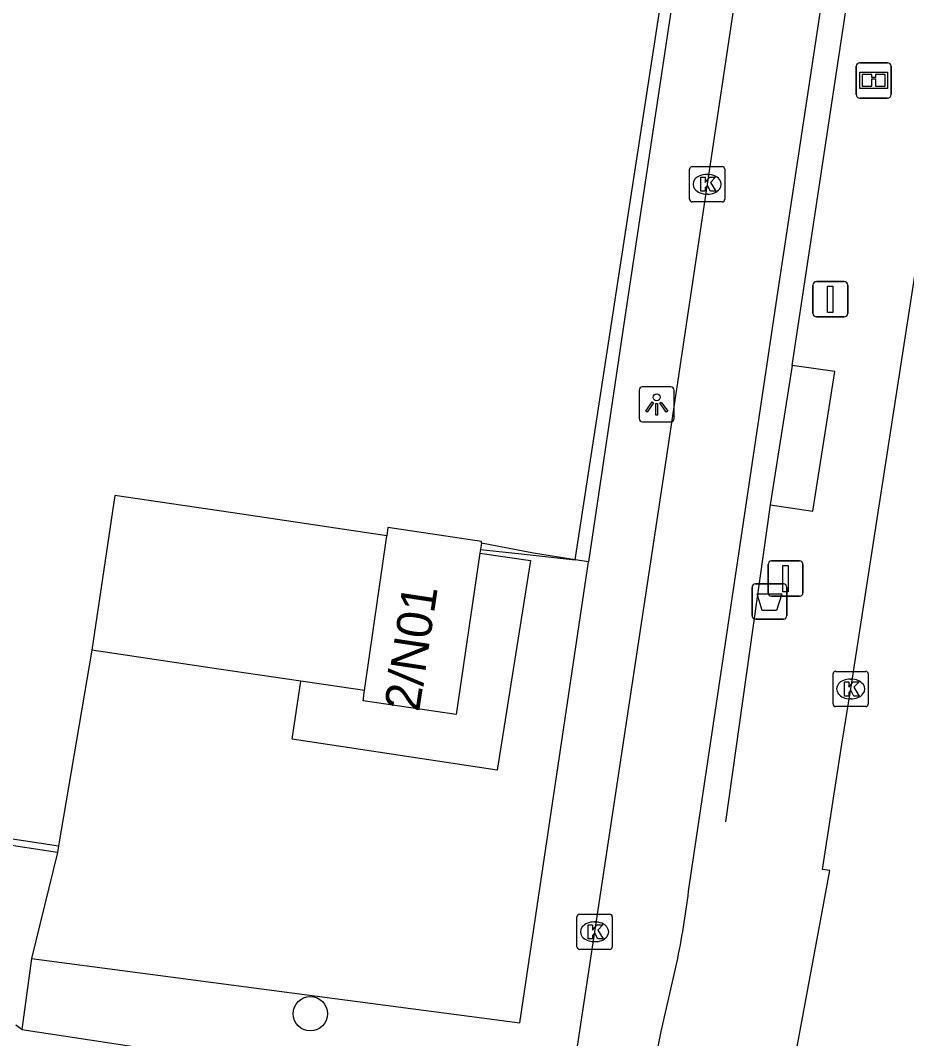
# Model space of a CAD drawing. Extents: x 161094 to 161705, y 379509 to 380907.
# Drawn here: x 161586.2 to 161611.36, y 380439.45 to 380468.34 of the extents above; entities that cross this region are included whole.
import ezdxf

# ---------------------------------------------------------------- set-up
doc = ezdxf.new("R2010")
doc.units = 0
for name, color, linetype in [('IMGEO_Afsluitpaal', 7, 'Continuous'), ('IMGEO_Afvalbak', 7, 'Continuous'), ('IMGEO_Boom', 7, 'Continuous'), ('IMGEO_Fietspad_gesloten', 7, 'Continuous'), ('IMGEO_Groenvoorziening', 7, 'Continuous'), ('IMGEO_Hek', 7, 'Continuous'), ('IMGEO_Informatiebord', 7, 'Continuous'), ('IMGEO_Kolk', 7, 'Continuous'), ('IMGEO_Lichtpunt', 7, 'Continuous'), ('IMGEO_Loofbos', 7, 'Continuous'), ('IMGEO_OVBaan_gesloten', 7, 'Continuous'), ('IMGEO_Pand', 7, 'Continuous'), ('IMGEO_Pand_nummerreeks', 7, 'Continuous'), ('IMGEO_Voetpad_open', 7, 'Continuous')]:
    doc.layers.add(name, color=color, linetype=linetype)

msp = doc.modelspace()

# ---------------------------------------------------------------- linework, layer by layer
at = {"layer": 'IMGEO_Afsluitpaal'}
for p, q in [((161608.694, 380460.028), (161608.694, 380460.828)), ((161608.694, 380460.828), (161608.694, 380460.028)), ((161608.794, 380460.928), (161609.584, 380460.928)), ((161609.584, 380460.928), (161608.794, 380460.928)), ((161609.684, 380460.828), (161609.684, 380460.028)), ((161609.684, 380460.028), (161609.684, 380460.828)), ((161609.584, 380459.928), (161608.794, 380459.928)), ((161608.794, 380459.928), (161609.584, 380459.928)), ((161607.424, 380452.103), (161607.424, 380452.903)), ((161607.424, 380452.903), (161607.424, 380452.103)), ((161607.524, 380453.003), (161608.314, 380453.003)), ((161608.314, 380453.003), (161607.524, 380453.003)), ((161608.414, 380452.903), (161608.414, 380452.103)), ((161608.414, 380452.103), (161608.414, 380452.903)), ((161608.314, 380452.003), (161607.524, 380452.003)), ((161607.524, 380452.003), (161608.314, 380452.003))]:
    msp.add_line(p, q, dxfattribs=at)
for points in [[(161609.114, 380460.803), (161609.264, 380460.803), (161609.264, 380460.053), (161609.114, 380460.053), (161609.114, 380460.803)], [(161607.844, 380452.878), (161607.994, 380452.878), (161607.994, 380452.128), (161607.844, 380452.128), (161607.844, 380452.878)]]:
    msp.add_lwpolyline(points, dxfattribs=at)
for centre, start, end in [((161608.794, 380460.828), 90, 180), ((161608.794, 380460.828), 90, 180), ((161609.584, 380460.828), 0, 90), ((161609.584, 380460.828), 360, 90), ((161608.794, 380460.028), 180, 270), ((161608.794, 380460.028), 180, 270), ((161609.584, 380460.028), 270, 0), ((161609.584, 380460.028), 270, 0), ((161607.524, 380452.903), 90, 180), ((161607.524, 380452.903), 90, 180), ((161608.314, 380452.903), 0, 90), ((161608.314, 380452.903), 360, 90), ((161607.524, 380452.103), 180, 270), ((161607.524, 380452.103), 180, 270), ((161608.314, 380452.103), 270, 0), ((161608.314, 380452.103), 270, 0)]:
    msp.add_arc(centre, 0.1, start, end, dxfattribs=at)
at = {"layer": 'IMGEO_Afvalbak'}
for p, q in [((161607.068, 380452.353), (161607.858, 380452.353)), ((161607.858, 380452.353), (161607.068, 380452.353)), ((161606.968, 380451.453), (161606.968, 380452.253)), ((161606.968, 380452.253), (161606.968, 380451.453)), ((161607.958, 380452.253), (161607.958, 380451.453)), ((161607.958, 380451.453), (161607.958, 380452.253)), ((161607.858, 380451.353), (161607.068, 380451.353)), ((161607.068, 380451.353), (161607.858, 380451.353))]:
    msp.add_line(p, q, dxfattribs=at)
msp.add_lwpolyline([(161607.111, 380452.067), (161607.815, 380452.067), (161607.666, 380451.597), (161607.26, 380451.597), (161607.111, 380452.067)], dxfattribs=at)
for centre, start, end in [((161607.068, 380452.253), 90, 180), ((161607.068, 380452.253), 90, 180), ((161607.858, 380452.253), 0, 90), ((161607.858, 380452.253), 360, 90), ((161607.068, 380451.453), 180, 270), ((161607.068, 380451.453), 180, 270), ((161607.858, 380451.453), 270, 0), ((161607.858, 380451.453), 270, 0)]:
    msp.add_arc(centre, 0.1, start, end, dxfattribs=at)
at = {"layer": 'IMGEO_Boom'}
msp.add_circle((161594.431, 380440.157), 0.489, dxfattribs=at)
at = {"layer": 'IMGEO_Fietspad_gesloten'}
for points in [[(161612.72, 380509.065), (161611.793, 380503.916), (161610.143, 380493.022), (161609.084, 380485.902), (161608.039, 380479.352), (161605.695, 380463.691), (161604.472, 380455.541), (161602.499, 380442.481), (161602, 380439.232)], [(161605.166, 380443.632), (161607.677, 380460.497), (161610.329, 380477.98), (161611.098, 380483.56)], [(161603.991, 380437.681), (161604.389, 380439.652), (161604.832, 380441.602)]]:
    msp.add_lwpolyline(points, dxfattribs=at)
msp.add_arc((161582.397, 380446.336), 22.929, 348.0854, 353.228, dxfattribs=at)
at = {"layer": 'IMGEO_Groenvoorziening'}
msp.add_lwpolyline([(161587.284, 380444.922), (161587.251, 380444.727)], dxfattribs=at)
at = {"layer": 'IMGEO_Hek'}
for points in [[(161599.258, 380453.328), (161600.417, 380453.203), (161601.946, 380453.038), (161608.829, 380497.747), (161609.712, 380502.964)], [(161608.111, 380458.552), (161611.815, 380483.076), (161613.253, 380482.731)], [(161587.251, 380444.727), (161434.436, 380467.982)], [(161607.482, 380454.596), (161606.219, 380445.605)], [(161588.227, 380450.468), (161587.284, 380444.922)], [(161587.284, 380444.922), (161587.251, 380444.727)]]:
    msp.add_lwpolyline(points, dxfattribs=at)
at = {"layer": 'IMGEO_Informatiebord'}
for p, q in [((161609.924, 380466.237), (161609.924, 380467.037)), ((161609.924, 380467.037), (161609.924, 380466.237)), ((161610.024, 380467.137), (161610.814, 380467.137)), ((161610.814, 380467.137), (161610.024, 380467.137)), ((161610.914, 380467.037), (161610.914, 380466.237)), ((161610.914, 380466.237), (161610.914, 380467.037)), ((161610.814, 380466.137), (161610.024, 380466.137)), ((161610.024, 380466.137), (161610.814, 380466.137))]:
    msp.add_line(p, q, dxfattribs=at)
for points in [[(161610.025, 380466.869), (161610.813, 380466.869), (161610.813, 380466.405), (161610.025, 380466.405), (161610.025, 380466.869)], [(161610.09, 380466.804), (161610.09, 380466.47), (161610.365, 380466.47), (161610.366, 380466.683), (161610.47, 380466.684), (161610.471, 380466.47), (161610.748, 380466.47), (161610.748, 380466.804), (161610.472, 380466.804), (161610.472, 380466.724), (161610.366, 380466.724), (161610.366, 380466.804), (161610.09, 380466.804)]]:
    msp.add_lwpolyline(points, dxfattribs=at)
for centre, start, end in [((161610.024, 380467.037), 90, 180), ((161610.024, 380467.037), 90, 180), ((161610.814, 380467.037), 0, 90), ((161610.814, 380467.037), 360, 90), ((161610.024, 380466.237), 180, 270), ((161610.024, 380466.237), 180, 270), ((161610.814, 380466.237), 270, 0), ((161610.814, 380466.237), 270, 0)]:
    msp.add_arc(centre, 0.1, start, end, dxfattribs=at)
at = {"layer": 'IMGEO_Kolk'}
for p, q in [((161605.269, 380464.191), (161606.121, 380464.191)), ((161605.194, 380463.265), (161605.194, 380464.117)), ((161605.682, 380463.971), (161605.707, 380463.971)), ((161606.195, 380464.117), (161606.195, 380463.265)), ((161605.705, 380463.411), (161605.68, 380463.411)), ((161606.121, 380463.191), (161605.269, 380463.191)), ((161609.267, 380448.945), (161609.267, 380449.797)), ((161609.342, 380449.871), (161610.194, 380449.871)), ((161610.268, 380449.797), (161610.268, 380448.945)), ((161609.755, 380449.651), (161609.78, 380449.651)), ((161610.194, 380448.871), (161609.342, 380448.871)), ((161609.778, 380449.091), (161609.753, 380449.091)), ((161601.998, 380442.055), (161601.998, 380442.907)), ((161602.073, 380442.981), (161602.925, 380442.981)), ((161602.999, 380442.907), (161602.999, 380442.055)), ((161602.486, 380442.761), (161602.511, 380442.761)), ((161602.509, 380442.201), (161602.484, 380442.201)), ((161602.925, 380441.981), (161602.073, 380441.981))]:
    msp.add_line(p, q, dxfattribs=at)
for points in [[(161605.269, 380464.191), (161606.121, 380464.191)], [(161605.194, 380463.265), (161605.194, 380464.117)], [(161605.515, 380463.891), (161605.638, 380463.891), (161605.638, 380463.74), (161605.768, 380463.891), (161605.932, 380463.891), (161605.786, 380463.74), (161605.939, 380463.491), (161605.787, 380463.491), (161605.702, 380463.655), (161605.638, 380463.588), (161605.638, 380463.491), (161605.515, 380463.491), (161605.515, 380463.891)], [(161606.195, 380464.117), (161606.195, 380463.265)], [(161606.121, 380463.191), (161605.269, 380463.191)], [(161609.267, 380448.945), (161609.267, 380449.797)], [(161609.342, 380449.871), (161610.194, 380449.871)], [(161610.268, 380449.797), (161610.268, 380448.945)], [(161609.588, 380449.571), (161609.711, 380449.571), (161609.711, 380449.42), (161609.841, 380449.571), (161610.005, 380449.571), (161609.859, 380449.42), (161610.012, 380449.171), (161609.86, 380449.171), (161609.775, 380449.335), (161609.711, 380449.268), (161609.711, 380449.171), (161609.588, 380449.171), (161609.588, 380449.571)], [(161610.194, 380448.871), (161609.342, 380448.871)], [(161601.998, 380442.055), (161601.998, 380442.907)], [(161602.073, 380442.981), (161602.925, 380442.981)], [(161602.999, 380442.907), (161602.999, 380442.055)], [(161602.319, 380442.681), (161602.442, 380442.681), (161602.442, 380442.53), (161602.572, 380442.681), (161602.736, 380442.681), (161602.59, 380442.53), (161602.743, 380442.281), (161602.591, 380442.281), (161602.506, 380442.445), (161602.442, 380442.378), (161602.442, 380442.281), (161602.319, 380442.281), (161602.319, 380442.681)], [(161602.925, 380441.981), (161602.073, 380441.981)]]:
    msp.add_lwpolyline(points, dxfattribs=at)
for centre, start, end in [((161605.271, 380464.115), 91.552, 178.448), ((161605.271, 380464.115), 91.552, 178.448), ((161606.119, 380464.115), 1.552, 88.448), ((161606.119, 380464.115), 1.552, 88.448), ((161605.271, 380463.267), 181.552, 268.448), ((161605.271, 380463.267), 181.552, 268.448), ((161606.119, 380463.267), 271.552, 358.448), ((161606.119, 380463.267), 271.552, 358.448), ((161609.344, 380449.795), 91.552, 178.448), ((161609.344, 380449.795), 91.552, 178.448), ((161610.192, 380449.795), 1.552, 88.448), ((161610.192, 380449.795), 1.552, 88.448), ((161609.344, 380448.947), 181.552, 268.448), ((161609.344, 380448.947), 181.552, 268.448), ((161610.192, 380448.947), 271.552, 358.448), ((161610.192, 380448.947), 271.552, 358.448), ((161602.075, 380442.905), 91.552, 178.448), ((161602.075, 380442.905), 91.552, 178.448), ((161602.923, 380442.905), 1.552, 88.448), ((161602.923, 380442.905), 1.552, 88.448), ((161602.075, 380442.057), 181.552, 268.448), ((161602.075, 380442.057), 181.552, 268.448), ((161602.923, 380442.057), 271.552, 358.448), ((161602.923, 380442.057), 271.552, 358.448)]:
    msp.add_arc(centre, 0.0765, start, end, dxfattribs=at)
for centre, major_axis, ratio, start_param, end_param in [((161605.681, 380463.691), (-0.387, 0.002), 0.722429, 4.712389, 7.853982), ((161605.706, 380463.691), (-0.39, 0.002), 0.717154, 1.570796, 4.712389), ((161609.754, 380449.371), (-0.387, 0.002), 0.722429, 4.712389, 7.853982), ((161609.779, 380449.371), (-0.39, 0.002), 0.717154, 1.570796, 4.712389), ((161602.485, 380442.481), (-0.387, 0.002), 0.722429, 4.712389, 7.853982), ((161602.51, 380442.481), (-0.39, 0.002), 0.717154, 1.570796, 4.712389)]:
    msp.add_ellipse(centre, major_axis=major_axis, ratio=ratio, start_param=start_param, end_param=end_param, dxfattribs=at)
at = {"layer": 'IMGEO_Lichtpunt'}
for p, q in [((161603.762, 380457.85), (161603.762, 380457.043)), ((161603.762, 380457.85), (161603.762, 380457.043)), ((161604.664, 380457.945), (161603.856, 380457.945)), ((161604.664, 380457.945), (161603.856, 380457.945)), ((161604.758, 380457.043), (161604.758, 380457.85)), ((161604.758, 380457.043), (161604.758, 380457.85)), ((161603.856, 380456.949), (161604.664, 380456.949)), ((161603.856, 380456.949), (161604.664, 380456.949))]:
    msp.add_line(p, q, dxfattribs=at)
for points in [[(161604.136, 380457.514), (161604.175, 380457.486), (161603.987, 380457.224), (161603.949, 380457.251), (161604.136, 380457.514)], [(161604.348, 380457.486), (161604.386, 380457.513), (161604.573, 380457.251), (161604.534, 380457.223), (161604.348, 380457.486)], [(161604.238, 380457.466), (161604.285, 380457.466), (161604.285, 380457.144), (161604.238, 380457.144), (161604.238, 380457.466)]]:
    msp.add_lwpolyline(points, dxfattribs=at)
msp.add_circle((161604.261, 380457.648), 0.0994, dxfattribs=at)
for centre, start, end in [((161603.856, 380457.85), 90, 180), ((161603.856, 380457.85), 90, 180), ((161604.664, 380457.85), 0, 90), ((161604.664, 380457.85), 0, 90), ((161603.856, 380457.043), 180, 270), ((161603.856, 380457.043), 180, 270), ((161604.664, 380457.043), 270, 0), ((161604.664, 380457.043), 270, 360)]:
    msp.add_arc(centre, 0.0946, start, end, dxfattribs=at)
at = {"layer": 'IMGEO_Loofbos'}
for points in [[(161434.559, 380468.215), (161434.68, 380468.197), (161437.88, 380467.708), (161447.798, 380466.193), (161450.466, 380465.785), (161459.238, 380464.445), (161462.434, 380463.956), (161476.893, 380461.747), (161480.056, 380461.264), (161486.843, 380460.227), (161490.036, 380459.739), (161500, 380458.218), (161504.1, 380457.592), (161587.284, 380444.922)], [(161587.251, 380444.727), (161434.436, 380467.982)], [(161602.323, 380452.975), (161601.946, 380453.038), (161600.762, 380453.225), (161599.284, 380453.506)], [(161588.227, 380450.468), (161587.284, 380444.922)], [(161587.251, 380444.727), (161586.511, 380441.722)]]:
    msp.add_lwpolyline(points, dxfattribs=at)
at = {"layer": 'IMGEO_OVBaan_gesloten'}
msp.add_lwpolyline([(161607.461, 380434.986), (161609.174, 380444.224), (161608.972, 380444.245), (161609.513, 380447.808), (161609.768, 380449.371), (161612.115, 380464.519), (161614.112, 380477.696), (161614.315, 380478.892), (161614.938, 380482.977)], dxfattribs=at)
at = {"layer": 'IMGEO_Pand'}
for points in [[(161596.599, 380453.72), (161592.486, 380454.328), (161588.877, 380454.862), (161588.227, 380450.468)], [(161599.284, 380453.506), (161599.292, 380453.559), (161596.632, 380453.952), (161596.599, 380453.72)], [(161595.968, 380449.323), (161596.599, 380453.72)], [(161599.284, 380453.506), (161599.243, 380453.228)], [(161599.243, 380453.228), (161598.566, 380448.646), (161595.926, 380449.037), (161595.968, 380449.323)], [(161594.16, 380449.59), (161591.835, 380449.934), (161588.227, 380450.468)], [(161595.968, 380449.323), (161594.16, 380449.59)]]:
    msp.add_lwpolyline(points, dxfattribs=at)
at = {"layer": 'IMGEO_Voetpad_open'}
for points in [[(161609.91, 380502.936), (161609.342, 380499.396), (161606.301, 380479.461), (161603.356, 380459.92), (161602.323, 380452.975)], [(161607.482, 380454.596), (161608.691, 380454.419), (161609.32, 380458.375), (161608.111, 380458.552), (161607.482, 380454.596)], [(161599.243, 380453.228), (161600.682, 380453.015), (161599.729, 380447.067), (161593.917, 380447.944), (161594.16, 380449.59)], [(161586.511, 380441.722), (161594.765, 380440.636), (161600.379, 380439.897), (161602.323, 380452.975)], [(161586.511, 380441.722), (161586.237, 380439.711)], [(161586.237, 380439.711), (161586.07, 380439.832)], [(161586.237, 380439.711), (161591.165, 380438.958), (161592.467, 380437.288)]]:
    msp.add_lwpolyline(points, dxfattribs=at)

# ---------------------------------------------------------------- texts
at = {"layer": 'IMGEO_Pand_nummerreeks'}
msp.add_text('2/N01', height=1, rotation=81.4058, dxfattribs=at).set_placement((161597.516, 380448.701))

doc.saveas('drawing.dxf')
